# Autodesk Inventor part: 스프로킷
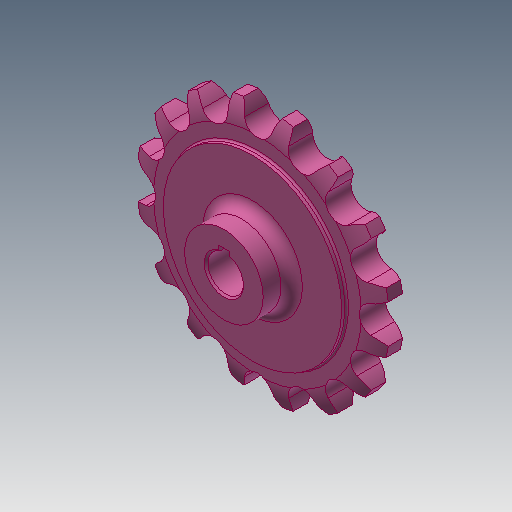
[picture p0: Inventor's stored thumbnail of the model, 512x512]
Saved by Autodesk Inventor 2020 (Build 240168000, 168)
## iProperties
Created: 2016-03
Part Number: 스프로킷
Material: 강철, 탄소
Document SubType Name: Modeling
Designer: mduedu
Density: 7.87 g/cm^3
Mass: 230.696 g
Surface Area: 96.4947 cm^2
Volume: 29.3133 cm^3
Appearance: 분홍색
Author: mduedu
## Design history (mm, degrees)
sketch "스케치1"
  geometry: L1 (0, 5)-(25, 5); L2 (25, 5)-(25, 4.1); L3 (25.5, 3.6)-(29.125, 3.6); L4 (35.5, 2)-(35.5, 0); L5 (35.5, 0)-(0, 0); L6 (0, 0)-(0, 5); L7 (0, -5)-(25, -5); L8 (25, -5)-(25, -4.1); L9 (25.5, -3.6)-(29.125, -3.6); L10 (35.5, -2)-(35.5, 0); L11 (0, 0)-(0, -5); A1 r 13.5 centre (29.125, -9.9) between (35.5, 2) and (29.125, 3.6); A2 r 13.5 centre (29.125, 9.9) between (29.125, -3.6) and (35.5, -2); A3 r 0.5 centre (25.5, 4.1) between (25, 4.1) and (25.5, 3.6); A4 r 0.5 centre (25.5, -4.1) between (25.5, -3.6) and (25, -4.1); 2 further points
  constraints: 22 end point, 8 point on circle, 6 symmetric about line, 5 tangent, 4 centre point, 4 parallel, 4 point on line, 1 equal radius, 1 horizontal, 1 perpendicular, 1 other
  dimensions: "d0" = 71 diameter of L4 L6; "d2" = 50 diameter of L2 L6; "d3" = 1.6 vertical distance of L4.start L3.end; "d4" = 3.6 distance from line of L4.end L3; "d5" = 5 distance between parallel lines of L5 L1; "d6" = 13.5 radius of A1; "d15" = 0.5 radius of A3
revolve "회전1" sketch "스케치1" stored, may be unused: angle "d7" = 90 deg
sketch "스케치2" dims "d8" = 57.16, "d11" = 71
  geometry: L1 (0, 0)-(0, 28.58); A1 r 32.55 centre (0, 0) between (-16.114, 28.281) and (0, 32.55); A2 r 3.97 centre (0, 32.55) between (-3.838, 31.533) and (0, 28.58); A3 r 12.7 centre (-16.114, 28.281) between (-3.838, 31.533) and (-5.392, 35.088); A4 r 12.7 centre (16.114, 28.281) between (5.392, 35.088) and (3.838, 31.533); A5 r 3.97 centre (0, 32.55) between (0, 28.58) and (3.838, 31.533); A6 r 35.5 centre (0, 0) between (5.392, 35.088) and (-5.392, 35.088); 2 further points
  constraints: 12 point on circle, 6 centre point, 4 coincident, 3 symmetric about line, 2 end point, 1 point on line, 1 tangent, 1 vertical, 1 vertical alignment, 7 other
  dimensions: "d10" = 65.1 diameter of A1; "d12" = 12.7 radius of A3
extrude "돌출1" cut sketch "스케치2" extent not by distance; stored distance "d13" = 10; taper "d14" = 0 deg
sketch "스케치3"
  geometry: C1 r 11 at (0, 0); 1 further point
  constraints: 1 centre point, 1 coincident
  dimensions: "d19" = 22 diameter of C1
extrude "돌출2" join sketch "스케치3" distance "d20" = 8; taper "d21" = 0 deg
fillet "모깎기1" dims "d22" = 3
sketch "스케치4"
  geometry: L1 (-1.5, 0)-(1.5, 0); L2 (1.5, 0)-(1.5, 6.4); L3 (1.5, 6.4)-(-1.5, 6.4); L4 (-1.5, 6.4)-(-1.5, 0); C1 r 5 at (0, 0); 2 further points
  constraints: 8 end point, 2 coincident, 2 parallel, 1 centre point, 1 horizontal, 1 midpoint, 1 perpendicular
  dimensions: "d23" = 10 diameter of C1; "d25" = 3 distance of L2.end L3.end; "d26" = 6.4 distance of L1.end L2.end
extrude "돌출3" cut sketch "스케치4" extent not by distance; stored distance "d27" = 8; taper "d28" = 0 deg
chamfer "모따기1" distance "d29" = 0.5; stored, may be unused: second distance "d30" = 2, angle "d31" = 45 deg
node "솔리드1"
pattern_circular "원형 패턴1" dims angle "d17" = 360 deg
